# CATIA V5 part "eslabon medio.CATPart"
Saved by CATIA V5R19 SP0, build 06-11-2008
Part number: eslabon medio
Bounding box of the stored display mesh (mm): x 215.134 to 240.534, y 457.655 to 1161.855, z 11027.612 to 11260.085
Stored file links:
  E:\Luis\Dropbox\3DIT\Parking\planos\cat 3 dit park8\eslabon medio.CATPart
  E:\Luis\Dropbox\3DIT\Parking\planos\cat 3 dit park8\Eslabon de Cadena.........................................CATProduct
  E:\Luis\Dropbox\3DIT\Parking\planos\cat 3 dit park8\ensamble unico eslabon.CATProduct
  E:\Luis\Dropbox\3DIT\Parking\planos\cat 3 dit park8\eslabon entre uniones.CATProduct
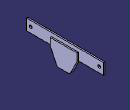
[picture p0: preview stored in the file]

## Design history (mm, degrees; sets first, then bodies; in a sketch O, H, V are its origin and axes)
External parameters (linked from other documents)
  External.p = 625
  External.b1 = 38.1
  External.b2 = 50.8
  External.d2 = 26.4
  External.g = 50.8
Body1 (main body)
  DatumSurface1
  DatumCurve1 to DatumCurve6
  Sketch1 on face of DatumSurface1, origin (227.8342, 0, 0), H (0, -1, 0), V (0, 0, 1)
    point P1 (-1122.2554, 11209.2854)
    point P2 (-497.2554, 11209.2854)
    line L1 (-1161.8554, 11260.0854) -> (-457.6554, 11260.0854)
    line L2 (-457.6554, 11260.0854) -> (-457.6554, 11158.4854)
    line L3 (-457.6554, 11158.4854) -> (-1161.8554, 11158.4854)
    line L4 (-1161.8554, 11158.4854) -> (-1161.8554, 11260.0854)
    reference projected line E1 (-1161.8554, 11234.6854) -> (-1161.8554, 11167.4854) from edge of DatumCurve4
    reference projected line E2 (-615.6554, 11260.0854) -> (-876.0554, 11260.0854) from edge of DatumCurve5
    reference projected line E3 (-876.0554, 11158.4854) -> (-708.2554, 11158.4854) from edge of DatumCurve6
    circle A1 centre (-1122.2554, 11209.2854) radius 13.2
    circle A2 centre (-497.2554, 11209.2854) radius 13.2
    distance L4 E1 = 0
    distance E2 L1 = 0
    distance L3 E3 = 0
    distance P2 P1 = 625 {= External.p /1000}
    distance L2 P2 = 39.6 {= External.d2 *1.5/1000}
    distance L4 P1 = 39.6 {= External.d2 *1.5/1000}
    distance P1 L3 = 50.8 {= External.g /1000}
    radius A2 = 13.2 {= External.d2 /2/1000}
    radius A1 = 13.2 {= External.d2 /1000/2}
    length L3 = 704.2 {= (External.p /1000) +(External.d2 *3/1000)}
    concentricity: P1 A1, P2 A2
    horizontal: L1 H, L3 H
    vertical: L2 V, L4 V
  Pad1: profile Sketch1, direction (-1, 0, 0), length 12.7
  DatumPoint1
  DatumPoint2
  DatumCurve7 to DatumCurve15
  Sketch2 on start face of Pad1, origin (227.8342, 0, 0), H (0, 1, 0), V (0, 0, 1)
    line L1 (687.6554, 11227.2506) -> (931.8554, 11227.2506)
    line L2 (931.8554, 11227.2506) -> (931.8554, 11160.2506)
    line L3 (687.6554, 11160.2506) -> (687.6554, 11227.2506)
    line L4 (767.9691, 11027.6124) -> (807.3596, 11027.6124)
    construction line L5 (809.7554, 11227.2506) -> (809.7554, 11292.1254)
    point P4 (809.7554, 11227.2506)
    reference projected circle E1 centre (497.2554, 11209.2854) radius 13.2 from edge [face of Pad1 from Sketch1.A2 | start face of Pad1]
    construction line L6 (497.2554, 11209.2854) -> (497.2554, 11303.91)
    point P6 (497.2554, 11209.2854)
    reference projected line E2 (460.6554, 11260.0854) -> (1161.8554, 11260.0854) from edge [start face of Pad1 | face of Pad1 from Sketch1.L1]
    reference projected line E3 (1161.8554, 11260.0854) -> (1161.8554, 11158.4854) from edge [start face of Pad1 | face of Pad1 from Sketch1.L4]
    line L7 (931.8554, 11160.2506) -> (874.0115, 11041.6531)
    point P8 (873.9167, 11041.4588)
    point P9 (931.8554, 11160.2506)
    line L8 (745.4993, 11041.6531) -> (687.6554, 11160.2506)
    point P10 (687.6554, 11160.2506)
    point P11 (867.1634, 11027.6124)
    point P13 (752.3474, 11027.6124)
    line L9 (807.3596, 11027.6124) -> (851.5416, 11027.6124)
    reference projected line E4 (1161.8554, 11158.4854) -> (460.6554, 11158.4854) from edge [start face of Pad1 | face of Pad1 from Sketch1.L3]
    arc A1 centre (851.5416, 11052.6124) radius 25 from (874.0115, 11041.6531) to (851.5416, 11027.6124) cw
    arc A2 centre (767.9691, 11052.6124) radius 25 from (767.9691, 11027.6124) to (745.4993, 11041.6531) cw
    distance L5 L6 = 312.5
    distance L1 E2 = 32.8347
    distance L2 E3 = 230
    length L3 = 67
    angle L8 L4 = 116
    angle L9 L7 = 116
    distance P13 L3 = 64.692
    distance P11 E4 = 130.873
    radius A1 = 25
    radius A2 = 25
    horizontal: L1 H
    vertical: L5 V, L6 V, L2 V, L3 V
    concentricity: P6 E1
    midpoint: P4 L1
    coincidence: P9 L7, P8 L7, L7 P11, L9 P11, L4 P13, L8 P13
    symmetry: P13 P11 L5, P10 P9 L5
    tangency: A1 L7, A1 L9, A2 L4, A2 L8
  Pad2: profile Sketch2, direction (1, 0, 0), length 12.7, mirrored extent
  DatumCurve16
  DatumSurface2
  DatumSurface3
  DatumCurve17
  DatumSurface4
  Sketch3 on DatumSurface4, origin (253.2342, 0, 0), H (0, -1, 0), V (0, 0, 1)
    reference projected circle E1 centre (-641.0554, 11209.2854) radius 12.7 from edge of DatumCurve17
    point P1 (-641.0554, 11209.2854)
    concentricity: P1 E1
